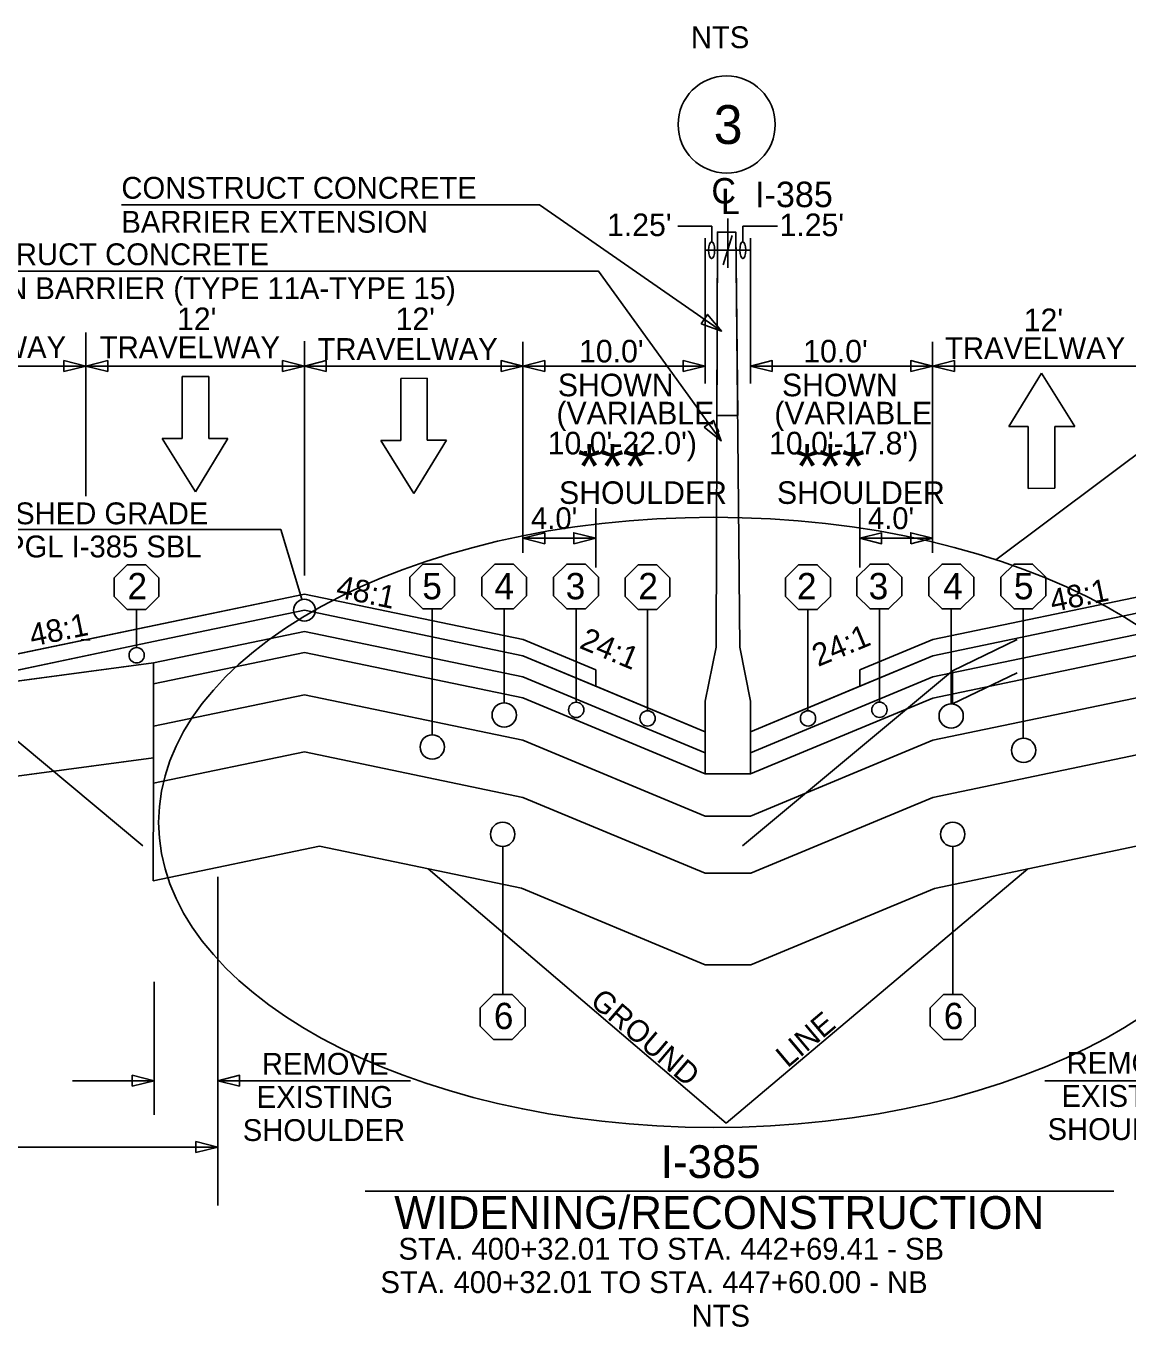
# Model space of a CAD drawing. Extents: x 4832 to 5477, y 4935 to 5220.
# Drawn here: x 5150.8 to 5211.3, y 5055.9 to 5127.3 of the extents above; entities that cross this region are included whole.
import ezdxf

# ---------------------------------------------------------------- set-up
doc = ezdxf.new("R2010")
doc.units = 0
for name, color, linetype in [('Level 2', 7, 'Continuous'), ('Level 25', 7, 'Continuous'), ('RD_QTY_Intermediate', 7, 'Continuous'), ('RD_QTY_Sub_Base', 7, 'Continuous'), ('RD_QTY_Surf_Course', 7, 'Continuous'), ('RD_SHT_Typical', 7, 'Continuous'), ('RD_TX_Misc1', 7, 'Continuous'), ('RD_TX_TypSect', 7, 'Continuous'), ('RD_XS_ExGround', 7, 'Continuous'), ('RD_XS_ExPaveRet', 7, 'Continuous'), ('RD_XS_Misc_Line', 7, 'Continuous'), ('TERMINATOR', 7, 'Continuous'), ('title', 7, 'Continuous'), ('typical_on', 7, 'Continuous')]:
    doc.layers.add(name, color=color, linetype=linetype)

# ---------------------------------------------------------------- blocks, each defined once
blk = doc.blocks.new('AH')
at = {"layer": 'TERMINATOR'}
blk.add_lwpolyline([(-6, 1.5), (0, 0), (-6, -1.5)], close=True, dxfattribs=at)

msp = doc.modelspace()

# ---------------------------------------------------------------- linework, layer by layer
at = {"layer": 'Level 2'}
for points in [[(5188.718, 5104.807), (5188.756, 5116.028), (5189.756, 5116.028), (5189.866, 5104.807)], [(5189.866, 5104.807), (5189.979, 5093.218), (5190.579, 5090.254), (5190.579, 5086.254), (5188.079, 5086.254), (5188.079, 5090.254), (5188.679, 5093.218), (5188.718, 5104.807)]]:
    msp.add_lwpolyline(points, dxfattribs=at)
msp.add_lwpolyline([(5188.718, 5105.954), (5188.756, 5116.028), (5189.756, 5116.028), (5189.866, 5105.954)], close=True, dxfattribs=at)
at = {"layer": 'Level 25'}
msp.add_circle((5189.261, 5121.935), 2.668, dxfattribs=at)
at = {"layer": 'RD_QTY_Intermediate'}
for p, q in [((5166.066, 5094.088), (5157.775, 5092.36)), ((5178.072, 5091.586), (5166.066, 5094.088)), ((5212.59, 5094.085), (5200.584, 5091.583)), ((5157.775, 5091.199), (5166.066, 5092.928)), ((5166.066, 5092.928), (5178.072, 5090.425)), ((5200.584, 5090.422), (5212.59, 5092.924)), ((5157.775, 5092.36), (5157.775, 5091.199)), ((5188.079, 5087.414), (5178.072, 5091.586)), ((5200.584, 5091.583), (5190.578, 5087.411)), ((5178.072, 5090.425), (5188.079, 5086.254)), ((5190.577, 5086.25), (5200.584, 5090.422)), ((5188.079, 5086.254), (5188.079, 5087.414))]:
    msp.add_line(p, q, dxfattribs=at)
msp.add_lwpolyline([(5190.578, 5087.411), (5190.578, 5087.411), (5190.577, 5086.25)], dxfattribs=at)
at = {"layer": 'RD_QTY_Sub_Base'}
for p, q in [((5166.066, 5087.467), (5157.764, 5085.737)), ((5178.072, 5084.965), (5166.066, 5087.467)), ((5212.59, 5087.464), (5200.584, 5084.961)), ((5157.764, 5085.737), (5157.763, 5080.374)), ((5188.075, 5080.795), (5178.072, 5084.965)), ((5200.584, 5084.961), (5190.581, 5080.791)), ((5157.763, 5080.374), (5166.9, 5082.278)), ((5166.9, 5082.278), (5177.983, 5079.968)), ((5200.674, 5079.965), (5211.756, 5082.275)), ((5190.581, 5080.791), (5188.075, 5080.795)), ((5177.983, 5079.968), (5188.073, 5075.762)), ((5190.584, 5075.759), (5200.674, 5079.965)), ((5188.073, 5075.762), (5190.584, 5075.759))]:
    msp.add_line(p, q, dxfattribs=at)
at = {"layer": 'RD_QTY_Surf_Course'}
for p, q in [((5166.066, 5095.249), (5157.775, 5093.521)), ((5178.072, 5092.747), (5166.066, 5095.249)), ((5212.59, 5095.246), (5200.584, 5092.743)), ((5157.775, 5092.36), (5166.066, 5094.088)), ((5166.066, 5094.088), (5178.072, 5091.586)), ((5200.584, 5091.583), (5212.59, 5094.085)), ((5157.775, 5093.521), (5142.054, 5090.244)), ((5142.054, 5090.244), (5157.775, 5092.36)), ((5178.072, 5091.586), (5188.079, 5087.414)), ((5190.578, 5087.411), (5200.584, 5091.583))]:
    msp.add_line(p, q, dxfattribs=at)
for points in [[(5188.079, 5088.575), (5182.065, 5091.082), (5178.072, 5092.747)], [(5200.584, 5092.743), (5196.574, 5091.072), (5190.578, 5088.572)], [(5188.079, 5087.414), (5188.079, 5088.575), (5188.079, 5088.575)], [(5190.578, 5088.572), (5190.578, 5088.572), (5190.578, 5087.411)]]:
    msp.add_lwpolyline(points, dxfattribs=at)
at = {"layer": 'RD_SHT_Typical'}
for p, q in [((5188.738, 5110.675), (5188.72, 5105.282)), ((5188.718, 5105.954), (5189.866, 5105.954)), ((5188.719, 5105.135), (5188.718, 5104.807)), ((5166.065, 5096.133), (5142.054, 5091.131)), ((5166.065, 5096.133), (5178.075, 5093.638)), ((5178.075, 5093.638), (5166.065, 5096.133)), ((5212.591, 5096.13), (5200.581, 5093.635)), ((5212.591, 5096.13), (5200.581, 5093.635)), ((5157.775, 5093.521), (5166.066, 5095.249)), ((5157.775, 5093.521), (5166.066, 5095.249)), ((5178.072, 5092.747), (5166.066, 5095.249)), ((5166.066, 5095.249), (5178.072, 5092.747)), ((5200.584, 5092.743), (5212.59, 5095.246)), ((5200.584, 5092.743), (5212.59, 5095.246)), ((5157.775, 5092.36), (5166.066, 5094.088)), ((5178.072, 5091.586), (5166.066, 5094.088)), ((5200.584, 5091.583), (5212.59, 5094.085)), ((5142.054, 5090.244), (5157.775, 5093.521)), ((5142.054, 5090.244), (5157.775, 5093.521)), ((5178.075, 5093.638), (5182.065, 5091.976)), ((5182.065, 5091.976), (5178.075, 5093.638)), ((5200.581, 5093.635), (5196.574, 5091.965)), ((5200.581, 5093.635), (5196.574, 5091.965)), ((5157.775, 5091.199), (5166.066, 5092.928)), ((5178.072, 5090.425), (5166.066, 5092.928)), ((5188.079, 5088.575), (5178.072, 5092.747)), ((5178.072, 5092.747), (5182.065, 5091.082)), ((5190.577, 5088.572), (5200.584, 5092.743)), ((5196.574, 5091.072), (5200.584, 5092.743)), ((5200.584, 5090.422), (5212.59, 5092.924)), ((5157.775, 5092.36), (5142.054, 5090.244)), ((5157.775, 5091.199), (5157.775, 5092.36)), ((5182.065, 5091.082), (5182.065, 5091.976)), ((5182.065, 5091.082), (5182.065, 5091.976)), ((5196.574, 5091.072), (5196.574, 5091.965)), ((5196.574, 5091.965), (5196.574, 5091.072)), ((5157.775, 5091.199), (5157.764, 5088.876)), ((5188.079, 5087.414), (5178.072, 5091.586)), ((5190.577, 5087.411), (5200.584, 5091.583)), ((5157.764, 5088.876), (5166.066, 5090.606)), ((5178.072, 5088.104), (5166.066, 5090.606)), ((5200.584, 5088.1), (5212.59, 5090.603)), ((5188.079, 5086.254), (5178.072, 5090.425)), ((5190.577, 5086.25), (5200.584, 5090.422)), ((5190.578, 5088.572), (5190.579, 5090.254)), ((5157.764, 5088.876), (5157.764, 5085.737)), ((5188.079, 5088.575), (5188.079, 5087.414)), ((5188.079, 5088.575), (5188.079, 5088.575)), ((5188.079, 5088.575), (5188.079, 5087.414)), ((5190.577, 5087.411), (5190.577, 5088.572)), ((5190.577, 5087.411), (5190.577, 5088.572)), ((5190.577, 5088.572), (5190.578, 5088.572)), ((5188.077, 5083.933), (5178.072, 5088.104)), ((5190.579, 5083.93), (5200.584, 5088.1)), ((5157.764, 5085.737), (5166.066, 5087.467)), ((5178.072, 5084.965), (5166.066, 5087.467)), ((5188.079, 5087.414), (5188.079, 5086.254)), ((5188.079, 5087.414), (5188.079, 5086.254)), ((5190.577, 5086.25), (5190.577, 5087.411)), ((5190.577, 5086.25), (5190.577, 5087.411)), ((5200.584, 5084.961), (5212.59, 5087.464)), ((5188.079, 5086.254), (5190.577, 5086.25)), ((5188.079, 5086.254), (5190.577, 5086.25)), ((5157.764, 5085.737), (5157.763, 5080.374)), ((5188.075, 5080.795), (5178.072, 5084.965)), ((5190.581, 5080.791), (5200.584, 5084.961)), ((5188.077, 5083.933), (5190.579, 5083.93)), ((5157.763, 5080.374), (5166.9, 5082.278)), ((5177.983, 5079.968), (5166.9, 5082.278)), ((5200.674, 5079.965), (5211.756, 5082.275)), ((5188.075, 5080.795), (5190.581, 5080.791)), ((5188.073, 5075.762), (5177.983, 5079.968)), ((5190.584, 5075.759), (5200.674, 5079.965)), ((5188.073, 5075.762), (5190.584, 5075.759))]:
    msp.add_line(p, q, dxfattribs=at)
for points in [[(5189.866, 5104.807), (5189.756, 5116.028), (5189.319, 5116.028), (5188.756, 5116.028), (5188.739, 5110.876)], [(5188.739, 5110.876), (5188.984, 5110.587), (5188.738, 5110.675)], [(5188.718, 5104.807), (5188.679, 5093.218), (5188.079, 5090.254), (5188.079, 5088.575)], [(5188.72, 5105.282), (5188.829, 5105.062), (5188.719, 5105.135)], [(5190.579, 5090.254), (5189.979, 5093.218), (5189.866, 5104.807)], [(5166.065, 5096.133), (5154.03, 5093.626), (5142.054, 5091.131)]]:
    msp.add_lwpolyline(points, dxfattribs=at)
at = {"layer": 'RD_TX_Misc1'}
for p, q in [((5159.347, 5108.083), (5160.805, 5108.092)), ((5159.347, 5104.68), (5159.347, 5108.083)), ((5160.805, 5104.689), (5160.805, 5108.092)), ((5171.353, 5107.982), (5172.811, 5107.991)), ((5171.353, 5104.578), (5171.353, 5107.982)), ((5172.811, 5104.588), (5172.811, 5107.991)), ((5206.556, 5108.267), (5204.771, 5105.34)), ((5208.38, 5105.35), (5206.556, 5108.267)), ((5205.828, 5105.34), (5204.771, 5105.34)), ((5205.828, 5105.34), (5205.828, 5101.937)), ((5207.286, 5105.349), (5208.38, 5105.35)), ((5207.286, 5105.349), (5207.286, 5101.946)), ((5159.347, 5104.68), (5158.253, 5104.679)), ((5158.253, 5104.679), (5160.077, 5101.762)), ((5160.077, 5101.762), (5161.862, 5104.689)), ((5160.805, 5104.689), (5161.862, 5104.689)), ((5171.353, 5104.578), (5170.259, 5104.578)), ((5170.259, 5104.578), (5172.083, 5101.661)), ((5172.083, 5101.661), (5173.868, 5104.588)), ((5172.811, 5104.588), (5173.868, 5104.588)), ((5207.286, 5101.946), (5205.828, 5101.937))]:
    msp.add_line(p, q, dxfattribs=at)
at = {"layer": 'RD_TX_TypSect'}
for p, q in [((5239.915, 5124.842), (5204.053, 5098.025)), ((5177.392, 5117.525), (5156.006, 5117.525)), ((5188.438, 5116.349), (5186.582, 5116.349)), ((5188.438, 5115.492), (5188.438, 5116.349)), ((5189.319, 5114.066), (5189.319, 5116.773)), ((5190.145, 5115.492), (5190.145, 5116.349)), ((5190.145, 5116.349), (5192.056, 5116.349)), ((5188.072, 5107.711), (5188.072, 5115.688)), ((5189.076, 5114.225), (5189.56, 5115.837)), ((5190.567, 5107.711), (5190.567, 5115.688)), ((5188.074, 5115.033), (5190.569, 5115.033)), ((5179.076, 5113.874), (5144.595, 5113.874)), ((5154.055, 5101.508), (5154.055, 5110.501)), ((5166.061, 5097.154), (5166.061, 5110.041)), ((5178.067, 5098.4), (5178.067, 5109.99)), ((5200.572, 5098.4), (5200.572, 5109.99)), ((5142.049, 5108.667), (5154.055, 5108.667)), ((5154.055, 5108.667), (5166.061, 5108.667)), ((5166.061, 5108.667), (5178.067, 5108.667)), ((5178.067, 5108.667), (5188.072, 5108.667)), ((5190.567, 5108.667), (5200.572, 5108.667)), ((5200.572, 5108.667), (5212.578, 5108.667)), ((5182.065, 5097.603), (5182.065, 5100.858)), ((5196.574, 5097.603), (5196.574, 5100.858)), ((5164.772, 5099.687), (5143.823, 5099.687)), ((5164.772, 5099.687), (5165.924, 5095.859)), ((5182.065, 5099.205), (5178.067, 5099.205)), ((5200.572, 5099.205), (5196.574, 5099.205)), ((5156.84, 5093.191), (5156.84, 5095.282)), ((5173.081, 5088.402), (5173.081, 5095.319)), ((5177.035, 5090.156), (5177.035, 5095.319)), ((5180.989, 5090.194), (5180.989, 5095.319)), ((5184.913, 5089.725), (5184.913, 5095.282)), ((5193.726, 5089.725), (5193.726, 5095.282)), ((5197.65, 5090.196), (5197.65, 5095.319)), ((5201.604, 5090.101), (5201.604, 5095.319)), ((5205.558, 5088.218), (5205.558, 5095.319)), ((5157.775, 5092.36), (5142.054, 5090.244)), ((5157.775, 5091.199), (5157.775, 5092.36)), ((5157.764, 5087.142), (5157.764, 5088.876)), ((5176.957, 5082.267), (5176.957, 5074.126)), ((5201.682, 5082.267), (5201.682, 5074.126)), ((5161.305, 5080.596), (5161.305, 5062.533)), ((5157.804, 5074.837), (5157.804, 5067.53)), ((5157.804, 5069.395), (5153.315, 5069.395)), ((5171.899, 5069.395), (5161.305, 5069.395)), ((5206.745, 5069.395), (5217.333, 5069.395)), ((5161.305, 5065.75), (5120.032, 5065.75)), ((5169.402, 5063.334), (5210.53, 5063.334))]:
    msp.add_line(p, q, dxfattribs=at)
for points in [[(5177.392, 5117.525), (5178.972, 5117.525), (5188.984, 5110.587)], [(5179.076, 5113.874), (5182.221, 5113.874), (5188.958, 5104.555)], [(5157.764, 5088.876), (5157.771, 5090.388), (5157.775, 5091.199)], [(5132.046, 5083.68), (5145.193, 5085.45), (5157.764, 5087.142)]]:
    msp.add_lwpolyline(points, dxfattribs=at)
for points in [[(5187.855, 5110.992), (5188.984, 5110.587), (5188.209, 5111.502)], [(5188.027, 5105.312), (5188.958, 5104.555), (5188.531, 5105.676)]]:
    msp.add_lwpolyline(points, close=True, dxfattribs=at)
for centre, radius in [((5166.066, 5095.249), 0.6), ((5156.847, 5092.771), 0.42), ((5177.039, 5089.489), 0.667), ((5177.039, 5089.489), 0.667), ((5180.994, 5089.774), 0.42), ((5184.918, 5089.305), 0.42), ((5193.73, 5089.305), 0.42), ((5197.653, 5089.776), 0.42), ((5197.653, 5089.776), 0.42), ((5201.594, 5089.434), 0.667), ((5201.594, 5089.434), 0.667), ((5173.086, 5087.735), 0.667), ((5173.086, 5087.735), 0.667), ((5205.573, 5087.551), 0.667), ((5205.573, 5087.551), 0.667), ((5176.957, 5082.934), 0.667), ((5176.957, 5082.934), 0.667), ((5201.682, 5082.934), 0.667), ((5201.682, 5082.934), 0.667)]:
    msp.add_circle(centre, radius, dxfattribs=at)
for centre, major_axis, ratio in [((5188.434, 5115.031), (0.004, 0.46), 0.357688), ((5190.149, 5115.031), (-0.004, 0.46), 0.357688), ((5188.544, 5083.592), (30.489, 0), 0.549804)]:
    msp.add_ellipse(centre, major_axis=major_axis, ratio=ratio, dxfattribs=at)
at = {"layer": 'RD_XS_ExGround'}
for p, q in [((5172.854, 5081.037), (5189.228, 5067.058)), ((5189.228, 5067.058), (5205.802, 5081.034))]:
    msp.add_line(p, q, dxfattribs=at)
at = {"layer": 'RD_XS_ExPaveRet'}
for p, q in [((5142.054, 5090.244), (5157.775, 5092.36)), ((5157.775, 5092.36), (5142.054, 5090.244)), ((5157.775, 5087.144), (5157.775, 5092.36)), ((5157.775, 5091.199), (5157.775, 5092.36)), ((5157.775, 5087.144), (5132.046, 5083.68))]:
    msp.add_line(p, q, dxfattribs=at)
for points in [[(5157.764, 5088.876), (5157.771, 5090.388), (5157.775, 5091.199)], [(5157.764, 5087.142), (5157.764, 5087.144), (5157.764, 5088.876)], [(5132.046, 5083.68), (5145.193, 5085.45), (5157.764, 5087.142)]]:
    msp.add_lwpolyline(points, dxfattribs=at)
at = {"layer": 'RD_XS_Misc_Line'}
for p, q in [((5205.217, 5093.631), (5201.667, 5091.92)), ((5145.663, 5091.923), (5157.191, 5082.311)), ((5201.667, 5091.92), (5190.139, 5082.308)), ((5201.667, 5091.92), (5201.667, 5090.096)), ((5205.217, 5091.807), (5201.667, 5090.096))]:
    msp.add_line(p, q, dxfattribs=at)
at = {"layer": 'title'}
msp.add_line((5153.802, 5093.626), (5154.302, 5093.626), dxfattribs=at)
at = {"layer": 'typical_on'}
for points in [[(5158.072, 5097.024), (5158.072, 5096.004), (5157.35, 5095.282), (5156.329, 5095.282), (5155.608, 5096.003), (5155.608, 5097.024), (5156.329, 5097.746), (5157.35, 5097.746)], [(5174.313, 5097.062), (5174.313, 5096.041), (5173.591, 5095.319), (5172.57, 5095.319), (5171.849, 5096.041), (5171.849, 5097.062), (5172.57, 5097.783), (5173.591, 5097.783)], [(5178.267, 5097.062), (5178.267, 5096.041), (5177.545, 5095.319), (5176.525, 5095.319), (5175.803, 5096.041), (5175.803, 5097.062), (5176.525, 5097.783), (5177.545, 5097.783)], [(5182.221, 5097.062), (5182.221, 5096.041), (5181.5, 5095.319), (5180.479, 5095.319), (5179.757, 5096.041), (5179.757, 5097.062), (5180.479, 5097.783), (5181.5, 5097.783)], [(5186.145, 5097.024), (5186.145, 5096.004), (5185.424, 5095.282), (5184.403, 5095.282), (5183.681, 5096.003), (5183.681, 5097.024), (5184.403, 5097.746), (5185.424, 5097.746)], [(5194.958, 5097.024), (5194.958, 5096.004), (5194.236, 5095.282), (5193.215, 5095.282), (5192.494, 5096.003), (5192.494, 5097.024), (5193.215, 5097.746), (5194.236, 5097.746)], [(5198.882, 5097.062), (5198.882, 5096.041), (5198.16, 5095.319), (5197.139, 5095.319), (5196.418, 5096.041), (5196.418, 5097.062), (5197.139, 5097.783), (5198.16, 5097.783)], [(5202.836, 5097.062), (5202.836, 5096.041), (5202.114, 5095.319), (5201.094, 5095.319), (5200.372, 5096.041), (5200.372, 5097.062), (5201.094, 5097.783), (5202.114, 5097.783)], [(5206.79, 5097.062), (5206.79, 5096.041), (5206.069, 5095.319), (5205.048, 5095.319), (5204.326, 5096.041), (5204.326, 5097.062), (5205.048, 5097.783), (5206.069, 5097.783)], [(5178.189, 5073.405), (5178.189, 5072.384), (5177.468, 5071.662), (5176.447, 5071.662), (5175.725, 5072.384), (5175.725, 5073.405), (5176.447, 5074.126), (5177.468, 5074.126)], [(5202.914, 5073.405), (5202.914, 5072.384), (5202.192, 5071.662), (5201.171, 5071.662), (5200.45, 5072.384), (5200.449, 5073.405), (5201.171, 5074.126), (5202.192, 5074.126)]]:
    msp.add_lwpolyline(points, close=True, dxfattribs=at)

# ---------------------------------------------------------------- block references
at = {"layer": 'RD_QTY_Surf_Course', "xscale": 0.20020004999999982, "yscale": -0.20020004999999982}
for p in [(5154.055, 5108.667), (5166.061, 5108.667), (5178.067, 5108.667), (5188.072, 5108.667), (5200.572, 5108.667), (5157.804, 5069.395), (5161.305, 5065.75)]:
    msp.add_blockref('AH', p, dxfattribs=at)
at = {"layer": 'RD_QTY_Surf_Course', "xscale": 0.20020004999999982, "yscale": 0.20020004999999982, "rotation": 180}
for p in [(5154.055, 5108.667), (5166.061, 5108.667), (5178.067, 5108.667), (5190.567, 5108.667), (5200.572, 5108.667), (5161.305, 5069.395)]:
    msp.add_blockref('AH', p, dxfattribs=at)
at = {"layer": 'TERMINATOR', "xscale": 0.2000217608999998, "yscale": -0.2000217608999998, "rotation": 180}
for p in [(5178.067, 5099.205), (5196.574, 5099.205)]:
    msp.add_blockref('AH', p, dxfattribs=at)
at = {"layer": 'TERMINATOR', "xscale": 0.2000217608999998, "yscale": -0.2000217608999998}
for p in [(5182.065, 5099.205), (5200.572, 5099.205)]:
    msp.add_blockref('AH', p, dxfattribs=at)

# ---------------------------------------------------------------- texts
at = {"layer": 'Level 25'}
msp.add_text('3', height=2.134, dxfattribs=at).set_placement((5188.547, 5120.868))
at = {"layer": 'RD_TX_TypSect'}
for s, height, p in [('NTS', 1.2, (5187.295, 5126.131)), ('CONSTRUCT CONCRETE', 1.20007, (5156.007, 5117.858)), ('C', 1.4, (5188.422, 5117.595)), ('L', 1.4, (5188.946, 5117.017)), ('I-385', 1.4, (5190.824, 5117.395)), ('BARRIER EXTENSION', 1.20007, (5156.007, 5115.991)), ("1.25'", 1.2407, (5182.69, 5115.805)), ("1.25'", 1.2407, (5192.166, 5115.805)), ('CONSTRUCT CONCRETE', 1.2, (5144.596, 5114.207)), ('MEDIAN BARRIER (TYPE 11A-TYPE 15)', 1.2, (5144.596, 5112.341)), ("12'", 1.2407, (5159.066, 5110.639)), ("12'", 1.2407, (5171.072, 5110.639)), ("12'", 1.2407, (5205.584, 5110.581)), ("10.0'", 1.2407, (5181.153, 5108.864)), ("10.0'", 1.2407, (5193.468, 5108.864)), ('SHOWN', 1.2407, (5179.986, 5107.003)), ('SHOWN', 1.2407, (5192.301, 5107.003)), ('(VARIABLE', 1.2407, (5179.911, 5105.462)), ('(VARIABLE', 1.2407, (5191.881, 5105.462)), ("10.0'-22.0')", 1.24068, (5179.431, 5103.811)), ("10.0'-17.8')", 1.24068, (5191.591, 5103.811)), ('***', 2.4431, (5181.075, 5101.937)), ('***', 2.4431, (5193.045, 5101.937)), ('SHOULDER', 1.2407, (5180.054, 5101.09)), ('SHOULDER', 1.2407, (5192.024, 5101.09)), ('2', 1.445, (5156.345, 5095.85)), ('5', 1.445, (5172.54, 5095.85)), ('4', 1.445, (5176.504, 5095.85)), ('3', 1.445, (5180.419, 5095.85)), ('2', 1.445, (5184.411, 5095.85)), ('2', 1.445, (5193.124, 5095.85)), ('3', 1.445, (5197.064, 5095.85)), ('4', 1.445, (5201.156, 5095.85)), ('5', 1.445, (5205.04, 5095.85)), ('6', 1.445, (5176.472, 5072.231)), ('6', 1.445, (5201.188, 5072.231)), ('I-385', 1.8, (5185.64, 5064.05)), ('WIDENING/RECONSTRUCTION', 1.8, (5170.999, 5061.252)), ('STA. 400+32.01 TO STA. 442+69.41 - SB', 1.2, (5171.23, 5059.562)), (' STA. 400+32.01 TO STA. 447+60.00 - NB', 1.2, (5169.796, 5057.728)), ('NTS', 1.2, (5187.334, 5055.881))]:
    msp.add_text(s, height=height, dxfattribs=at).set_placement(p)
for s, height, rotation, p in [('TRAVELWAY', 1.2001, 359.99858, (5143.072, 5109.099)), ('TRAVELWAY', 1.2001, 359.99858, (5154.823, 5109.094)), ('TRAVELWAY', 1.2001, 359.99858, (5166.784, 5108.999)), ('TRAVELWAY', 1.2001, 359.99858, (5201.262, 5109.048)), ('FINISHED GRADE', 1.20007, 360, (5147.143, 5099.971)), ("4.0'", 1.2, 359.99858, (5178.515, 5099.702)), ("4.0'", 1.2, 359.99858, (5197.022, 5099.702)), ('POINT PGL I-385 SBL', 1.20007, 360, (5144.27, 5098.151)), ('48:1', 1.2407, 348.32401, (5167.749, 5095.97)), ('48:1', 1.2407, 11.67599, (5207.166, 5095.14)), ('48:1', 1.2407, 11.67599, (5151.098, 5093.243)), ('24:1', 1.2407, 337.38196, (5181.114, 5093.191)), ('24:1', 1.2407, 22.61804, (5194.285, 5092.126)), ('GROUND', 1.2, 319.51056, (5181.698, 5073.644)), ('LINE', 1.2, 40.13797, (5192.608, 5070.066)), ('REMOVE', 1.2001, 360, (5163.725, 5069.724)), ('REMOVE', 1.2001, 360, (5207.94, 5069.778)), ('EXISTING', 1.2001, 360, (5163.442, 5067.904)), ('EXISTING', 1.2001, 360, (5207.657, 5067.957)), ('SHOULDER', 1.2001, 360, (5162.676, 5066.083)), ('SHOULDER', 1.2001, 360, (5206.891, 5066.137))]:
    msp.add_text(s, height=height, rotation=rotation, dxfattribs=at).set_placement(p)

doc.saveas('drawing.dxf')
